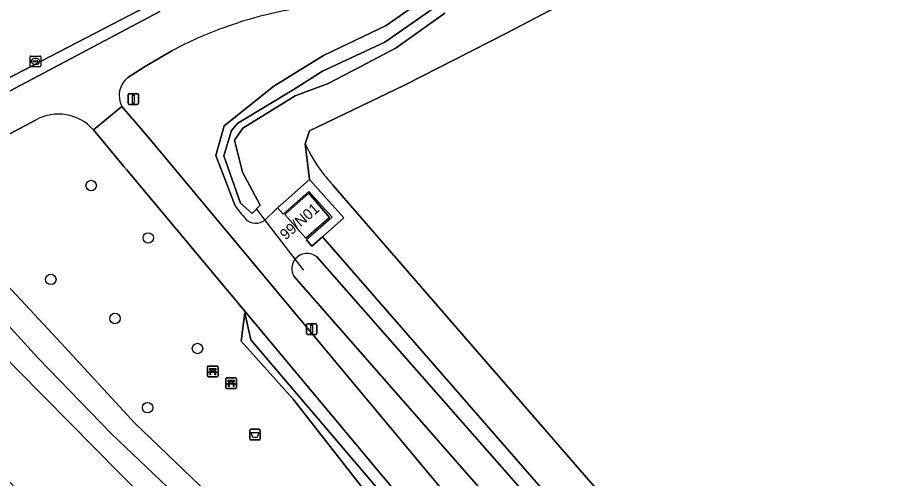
# Model space of a CAD drawing. Extents: x 156061 to 157804, y 383437 to 385640.
# Drawn here: x 156111.7 to 156194.1, y 385328.5 to 385371.7 of the extents above; entities that cross this region are included whole.
import ezdxf

# ---------------------------------------------------------------- set-up
doc = ezdxf.new("R2010")
doc.units = 0
for name, color, linetype in [('IMGEO_Afvalbak', 7, 'Continuous'), ('IMGEO_Bank', 7, 'Continuous'), ('IMGEO_Berm_groen', 7, 'Continuous'), ('IMGEO_Boom', 7, 'Continuous'), ('IMGEO_Duiker', 7, 'Continuous'), ('IMGEO_Fietspad_gesloten', 7, 'Continuous'), ('IMGEO_Groenvoorziening', 7, 'Continuous'), ('IMGEO_Kolk', 7, 'Continuous'), ('IMGEO_Lichtmast', 7, 'Continuous'), ('IMGEO_Loofbos', 7, 'Continuous'), ('IMGEO_Muur', 7, 'Continuous'), ('IMGEO_Oever', 7, 'Continuous'), ('IMGEO_Pand', 7, 'Continuous'), ('IMGEO_Pand_nummerreeks', 7, 'Continuous'), ('IMGEO_Rijbaan_lokaal_gesloten', 7, 'Continuous'), ('IMGEO_Rijbaan_lokaal_open', 7, 'Continuous'), ('IMGEO_Rijbaan_regionaal_gesloten', 7, 'Continuous'), ('IMGEO_Waterloop', 7, 'Continuous')]:
    doc.layers.add(name, color=color, linetype=linetype)

msp = doc.modelspace()

# ---------------------------------------------------------------- linework, layer by layer
at = {"layer": 'IMGEO_Afvalbak'}
for p, q in [((156133.502, 385332.24), (156133.502, 385333.04)), ((156133.502, 385333.04), (156133.502, 385332.24)), ((156133.602, 385333.14), (156134.392, 385333.14)), ((156134.392, 385333.14), (156133.602, 385333.14)), ((156134.492, 385333.04), (156134.492, 385332.24)), ((156134.492, 385332.24), (156134.492, 385333.04)), ((156134.392, 385332.14), (156133.602, 385332.14)), ((156133.602, 385332.14), (156134.392, 385332.14))]:
    msp.add_line(p, q, dxfattribs=at)
msp.add_lwpolyline([(156133.645, 385332.854), (156134.349, 385332.854), (156134.2, 385332.384), (156133.794, 385332.384), (156133.645, 385332.854)], dxfattribs=at)
for centre, start, end in [((156133.602, 385333.04), 90, 180), ((156133.602, 385333.04), 90, 180), ((156134.392, 385333.04), 0, 90), ((156134.392, 385333.04), 360, 90), ((156133.602, 385332.24), 180, 270), ((156133.602, 385332.24), 180, 270), ((156134.392, 385332.24), 270, 0), ((156134.392, 385332.24), 270, 0)]:
    msp.add_arc(centre, 0.1, start, end, dxfattribs=at)
at = {"layer": 'IMGEO_Bank'}
for p, q in [((156129.534, 385338.142), (156129.534, 385338.983)), ((156129.534, 385338.983), (156129.534, 385338.142)), ((156129.609, 385339.067), (156130.45, 385339.067)), ((156130.45, 385339.067), (156129.609, 385339.067)), ((156130.231, 385338.465), (156129.838, 385338.465)), ((156129.843, 385338.573), (156129.843, 385338.679)), ((156129.887, 385338.679), (156129.887, 385338.573)), ((156130.175, 385338.685), (156129.893, 385338.685)), ((156129.893, 385338.567), (156130.175, 385338.567)), ((156130.181, 385338.573), (156130.181, 385338.679)), ((156130.225, 385338.679), (156130.225, 385338.573)), ((156130.534, 385338.992), (156130.534, 385338.151)), ((156130.534, 385338.151), (156130.534, 385338.992)), ((156130.459, 385338.067), (156129.618, 385338.067)), ((156129.618, 385338.067), (156130.459, 385338.067)), ((156131.264, 385337.033), (156131.264, 385337.874)), ((156131.264, 385337.874), (156131.264, 385337.033)), ((156131.339, 385337.958), (156132.18, 385337.958)), ((156132.18, 385337.958), (156131.339, 385337.958)), ((156132.264, 385337.883), (156132.264, 385337.042)), ((156132.264, 385337.042), (156132.264, 385337.883)), ((156132.189, 385336.958), (156131.348, 385336.958)), ((156131.348, 385336.958), (156132.189, 385336.958)), ((156131.961, 385337.356), (156131.568, 385337.356)), ((156131.573, 385337.464), (156131.573, 385337.57)), ((156131.617, 385337.57), (156131.617, 385337.464)), ((156131.905, 385337.576), (156131.623, 385337.576)), ((156131.623, 385337.458), (156131.905, 385337.458)), ((156131.911, 385337.464), (156131.911, 385337.57)), ((156131.955, 385337.57), (156131.955, 385337.464))]:
    msp.add_line(p, q, dxfattribs=at)
for points in [[(156129.781, 385338.465), (156129.639, 385338.465), (156129.751, 385338.567), (156129.837, 385338.567)], [(156129.837, 385338.685), (156129.751, 385338.685), (156129.751, 385338.846), (156130.314, 385338.846), (156130.314, 385338.685), (156130.231, 385338.685)], [(156129.831, 385338.458), (156129.831, 385338.251), (156129.788, 385338.251), (156129.788, 385338.458)], [(156130.231, 385338.567), (156130.314, 385338.567), (156130.426, 385338.465), (156130.287, 385338.465)], [(156130.281, 385338.458), (156130.281, 385338.251), (156130.237, 385338.251), (156130.237, 385338.458)], [(156131.567, 385337.576), (156131.481, 385337.576), (156131.481, 385337.737), (156132.044, 385337.737), (156132.044, 385337.576), (156131.961, 385337.576)], [(156131.511, 385337.356), (156131.369, 385337.356), (156131.481, 385337.458), (156131.567, 385337.458)], [(156131.561, 385337.349), (156131.561, 385337.142), (156131.518, 385337.142), (156131.518, 385337.349)], [(156131.961, 385337.458), (156132.044, 385337.458), (156132.156, 385337.356), (156132.017, 385337.356)], [(156132.011, 385337.349), (156132.011, 385337.142), (156131.967, 385337.142), (156131.967, 385337.349)]]:
    msp.add_lwpolyline(points, dxfattribs=at)
for centre, radius, start, end in [((156129.612, 385338.989), 0.0779, 92.4484, 184.28452), ((156129.612, 385338.989), 0.0779, 92.4484, 184.28452), ((156129.781, 385338.458), 0.00671, 2.89567, 87.10433), ((156129.838, 385338.458), 0.00671, 92.89567, 177.10433), ((156129.836, 385338.678), 0.00671, 2.89567, 87.10433), ((156129.836, 385338.574), 0.00671, 272.89567, 357.10433), ((156129.893, 385338.678), 0.00671, 92.89567, 177.10433), ((156129.893, 385338.574), 0.00671, 182.89567, 267.10433), ((156130.175, 385338.678), 0.00671, 2.89567, 87.10433), ((156130.175, 385338.574), 0.00671, 272.89567, 357.10433), ((156130.232, 385338.678), 0.00671, 92.89567, 177.10433), ((156130.232, 385338.574), 0.00671, 182.89567, 267.10433), ((156130.23, 385338.458), 0.00671, 2.89567, 87.10433), ((156130.287, 385338.458), 0.00671, 92.89567, 177.10433), ((156130.456, 385338.989), 0.0779, 2.4484, 94.28452), ((156130.456, 385338.989), 0.0779, 2.4484, 94.28452), ((156129.612, 385338.145), 0.0779, 182.4484, 274.28452), ((156129.612, 385338.145), 0.0779, 182.4484, 274.28452), ((156130.456, 385338.145), 0.0779, 272.4484, 4.28452), ((156130.456, 385338.145), 0.0779, 272.4484, 4.28452), ((156131.342, 385337.88), 0.0779, 92.4484, 184.28452), ((156131.342, 385337.88), 0.0779, 92.4484, 184.28452), ((156132.186, 385337.88), 0.0779, 2.4484, 94.28452), ((156132.186, 385337.88), 0.0779, 2.4484, 94.28452), ((156131.342, 385337.036), 0.0779, 182.4484, 274.28452), ((156131.342, 385337.036), 0.0779, 182.4484, 274.28452), ((156131.511, 385337.349), 0.00671, 2.89567, 87.10433), ((156131.568, 385337.349), 0.00671, 92.89567, 177.10433), ((156131.566, 385337.569), 0.00671, 2.89567, 87.10433), ((156131.566, 385337.465), 0.00671, 272.89567, 357.10433), ((156131.623, 385337.569), 0.00671, 92.89567, 177.10433), ((156131.623, 385337.465), 0.00671, 182.89567, 267.10433), ((156131.905, 385337.569), 0.00671, 2.89567, 87.10433), ((156131.905, 385337.465), 0.00671, 272.89567, 357.10433), ((156131.962, 385337.569), 0.00671, 92.89567, 177.10433), ((156131.962, 385337.465), 0.00671, 182.89567, 267.10433), ((156131.96, 385337.349), 0.00671, 2.89567, 87.10433), ((156132.017, 385337.349), 0.00671, 92.89567, 177.10433), ((156132.186, 385337.036), 0.0779, 272.4484, 4.28452), ((156132.186, 385337.036), 0.0779, 272.4484, 4.28452)]:
    msp.add_arc(centre, radius, start, end, dxfattribs=at)
at = {"layer": 'IMGEO_Berm_groen'}
msp.add_lwpolyline([(156362.884, 385518.973), (156357.592, 385515.726), (156355.546, 385514.471), (156333.022, 385500.076), (156304.543, 385485.405), (156304.354, 385485.797), (156253.2, 385452.656), (156166.982, 385396.482), (156160.762, 385392.485), (156159.544, 385391.815), (156159.731, 385391.428), (156152.382, 385387.554), (156100.569, 385360.692), (156097.06, 385358.974), (156097.829, 385357.837), (156097.994, 385357.927), (156125.069, 385372.264)], dxfattribs=at)
at = {"layer": 'IMGEO_Boom'}
for centre in [(156118.643, 385355.969), (156123.994, 385351.065), (156114.858, 385347.18), (156120.874, 385343.522), (156128.607, 385340.709), (156123.933, 385335.169)]:
    msp.add_circle(centre, 0.489, dxfattribs=at)
at = {"layer": 'IMGEO_Duiker'}
msp.add_lwpolyline([(156134.122, 385353.757), (156134.914, 385352.731), (156137.743, 385349.064), (156138.528, 385348.047)], dxfattribs=at)
at = {"layer": 'IMGEO_Fietspad_gesloten'}
for points in [[(156125.069, 385372.264), (156097.994, 385357.927), (156097.829, 385357.837), (156095.409, 385356.512), (156096.045, 385355.752), (156098.015, 385353.552), (156101.468, 385355.413), (156101.871, 385355.645), (156108.986, 385359.742), (156113.433, 385362.1)], [(156122.086, 385366.08), (156123.812, 385367.192), (156126.209, 385368.594)], [(156124.171, 385360.272), (156123.473, 385361.108), (156121.522, 385363.38), (156118.856, 385361.174), (156121.706, 385357.754), (156121.942, 385357.471), (156177.328, 385291.209)], [(156118.856, 385361.174), (156121.522, 385363.38)], [(156180.981, 385292.496), (156180.803, 385292.737), (156151.782, 385327.202), (156124.171, 385360.272)]]:
    msp.add_lwpolyline(points, dxfattribs=at)
for centre, radius, start, end in [((156144.397, 385334.134), 38.966, 100.19662, 109.99344), ((156144.386, 385334.178), 38.921, 110.00054, 117.84136), ((156123.412, 385364.394), 2.145, 128.18771, 208.2147), ((156115.576, 385358.305), 4.358, 41.16871, 119.45122)]:
    msp.add_arc(centre, radius, start, end, dxfattribs=at)
at = {"layer": 'IMGEO_Groenvoorziening'}
for points in [[(156132.124, 385354.072), (156130.332, 385358.77), (156131.122, 385361.565), (156135.769, 385365.262), (156140.41, 385368.141), (156146.274, 385370.967), (156151.561, 385374.676)], [(156126.209, 385368.594), (156123.812, 385367.192), (156122.086, 385366.08)], [(156121.522, 385363.38), (156123.473, 385361.108), (156124.171, 385360.272), (156151.782, 385327.202)], [(156113.433, 385362.1), (156108.986, 385359.742)], [(156177.328, 385291.209), (156121.942, 385357.471), (156121.706, 385357.754), (156118.856, 385361.174)], [(156138.687, 385359.878), (156139.112, 385356.54), (156142.328, 385352.959), (156140.316, 385351.172), (156228.502, 385250), (156247.683, 385227.995), (156253.968, 385221.655), (156275.143, 385200.293), (156292.679, 385186.81), (156309.519, 385180.688), (156293.366, 385188.187), (156275.563, 385201.731)], [(156275.563, 385201.731), (156250.074, 385230.682), (156233.307, 385250), (156141.333, 385355.967)], [(156308.967, 385179.207), (156309.519, 385180.688), (156292.679, 385186.81), (156275.143, 385200.293), (156253.968, 385221.655), (156247.683, 385227.995), (156228.502, 385250), (156140.316, 385351.172), (156139.329, 385350.295), (156138.808, 385350.896), (156141.213, 385353.008), (156139.055, 385355.418), (156136.634, 385353.281), (156136.104, 385353.881), (156134.914, 385352.731)], [(156132.278, 385307.447), (156166.281, 385278.086), (156168.774, 385281.118), (156168.451, 385282.676), (156168.153, 385284.113), (156128.476, 385321.756), (156111.805, 385338.65), (156108.949, 385341.526), (156101.165, 385350.479), (156102.695, 385354.328), (156092.828, 385348.213)], [(156106.557, 385351.121), (156115.827, 385341.223), (156122.749, 385333.724), (156145.451, 385311.967), (156161.597, 385296.852), (156167.136, 385291.02), (156170.907, 385294.205), (156167.577, 385298.602), (156152.558, 385316.809)], [(156108.949, 385341.526), (156111.805, 385338.65), (156128.476, 385321.756), (156168.153, 385284.113), (156168.051, 385284.608), (156168.579, 385286.057), (156165.732, 385289.28), (156159.247, 385295.892), (156120.561, 385332.702), (156113.657, 385339.835), (156104.831, 385349.468)], [(156139.813, 385349.261), (156227.178, 385250)], [(156244.566, 385225.657), (156223.173, 385250), (156160.289, 385321.652), (156137.62, 385347.482)], [(156152.558, 385316.809), (156137.58, 385335.954), (156132.713, 385341.392), (156133.03, 385344.043), (156133.592, 385341.527), (156173.944, 385294.235), (156176.282, 385291.491)]]:
    msp.add_lwpolyline(points, dxfattribs=at)
msp.add_lwpolyline([(156140.985, 385352.992), (156138.774, 385351.041), (156136.784, 385353.269), (156139.027, 385355.243)], close=True, dxfattribs=at)
for centre, radius, start, end in [((156144.397, 385334.134), 38.966, 100.19662, 109.99344), ((156144.386, 385334.178), 38.921, 110.00054, 117.84136), ((156123.412, 385364.394), 2.145, 128.18771, 208.2147), ((156115.576, 385358.305), 4.358, 41.16871, 119.45122), ((156153.941, 385367.252), 16.943, 205.79963, 217.02343), ((156153.76, 385367.443), 16.915, 217.91063, 222.72317), ((156145.275, 385363.705), 16.302, 216.22196, 221.88639), ((156134.079, 385353.813), 1.366, 226.53175, 307.66295), ((156138.871, 385348.189), 1.427, 48.66865, 142.20418), ((156138.862, 385348.181), 1.425, 141.72781, 209.38062), ((156444.762, 385648.913), 462.867, 222.80362, 227.53759)]:
    msp.add_arc(centre, radius, start, end, dxfattribs=at)
at = {"layer": 'IMGEO_Kolk'}
for p, q in [((156112.991, 385368.095), (156113.843, 385368.095)), ((156112.916, 385367.169), (156112.916, 385368.021)), ((156113.175, 385367.589), (156113.175, 385367.601)), ((156113.613, 385367.552), (156113.215, 385367.552)), ((156113.218, 385367.638), (156113.616, 385367.638)), ((156113.427, 385367.315), (156113.402, 385367.315)), ((156113.404, 385367.875), (156113.429, 385367.875)), ((156113.659, 385367.601), (156113.659, 385367.589)), ((156113.917, 385368.021), (156113.917, 385367.169)), ((156113.843, 385367.095), (156112.991, 385367.095))]:
    msp.add_line(p, q, dxfattribs=at)
for points in [[(156112.991, 385368.095), (156113.843, 385368.095)], [(156112.916, 385367.169), (156112.916, 385368.021)], [(156113.917, 385368.021), (156113.917, 385367.169)], [(156113.843, 385367.095), (156112.991, 385367.095)]]:
    msp.add_lwpolyline(points, dxfattribs=at)
for centre, radius, start, end in [((156112.993, 385368.019), 0.0765, 91.55205, 178.44795), ((156112.993, 385368.019), 0.0765, 91.55205, 178.44795), ((156113.841, 385368.019), 0.0765, 1.55205, 88.44795), ((156113.841, 385368.019), 0.0765, 1.55205, 88.44795), ((156113.215, 385367.598), 0.0403, 85.87752, 175.75265), ((156113.212, 385367.588), 0.0366, 178.93798, 274.71019), ((156113.616, 385367.595), 0.043, 264.86636, 352.45326), ((156113.62, 385367.6), 0.0386, 1.73085, 96.63898), ((156112.993, 385367.171), 0.0765, 181.55205, 268.44795), ((156112.993, 385367.171), 0.0765, 181.55205, 268.44795), ((156113.841, 385367.171), 0.0765, 271.55205, 358.44795), ((156113.841, 385367.171), 0.0765, 271.55205, 358.44795)]:
    msp.add_arc(centre, radius, start, end, dxfattribs=at)
for centre, major_axis, ratio, start_param, end_param in [((156113.403, 385367.595), (-0.387, 0.002), 0.722429, 4.712389, 7.853982), ((156113.428, 385367.595), (-0.39, 0.002), 0.717154, 1.570796, 4.712389)]:
    msp.add_ellipse(centre, major_axis=major_axis, ratio=ratio, start_param=start_param, end_param=end_param, dxfattribs=at)
at = {"layer": 'IMGEO_Lichtmast'}
for p, q in [((156122.098, 385363.672), (156122.098, 385364.472)), ((156122.098, 385364.472), (156122.098, 385363.672)), ((156122.198, 385364.572), (156122.988, 385364.572)), ((156122.988, 385364.572), (156122.198, 385364.572)), ((156123.088, 385364.472), (156123.088, 385363.672)), ((156123.088, 385363.672), (156123.088, 385364.472)), ((156122.988, 385363.572), (156122.198, 385363.572)), ((156122.198, 385363.572), (156122.988, 385363.572)), ((156138.814, 385342.126), (156138.814, 385342.926)), ((156138.814, 385342.926), (156138.814, 385342.126)), ((156138.914, 385343.026), (156139.704, 385343.026)), ((156139.704, 385343.026), (156138.914, 385343.026)), ((156139.804, 385342.926), (156139.804, 385342.126)), ((156139.804, 385342.126), (156139.804, 385342.926)), ((156139.704, 385342.026), (156138.914, 385342.026)), ((156138.914, 385342.026), (156139.704, 385342.026))]:
    msp.add_line(p, q, dxfattribs=at)
for points in [[(156122.518, 385364.447), (156122.668, 385364.447), (156122.668, 385363.697), (156122.518, 385363.697), (156122.518, 385364.447)], [(156139.234, 385342.901), (156139.384, 385342.901), (156139.384, 385342.151), (156139.234, 385342.151), (156139.234, 385342.901)]]:
    msp.add_lwpolyline(points, dxfattribs=at)
for centre, start, end in [((156122.198, 385364.472), 90, 180), ((156122.198, 385364.472), 90, 180), ((156122.988, 385364.472), 0, 90), ((156122.988, 385364.472), 360, 90), ((156122.198, 385363.672), 180, 270), ((156122.198, 385363.672), 180, 270), ((156122.988, 385363.672), 270, 0), ((156122.988, 385363.672), 270, 0), ((156138.914, 385342.926), 90, 180), ((156138.914, 385342.926), 90, 180), ((156139.704, 385342.926), 0, 90), ((156139.704, 385342.926), 360, 90), ((156138.914, 385342.126), 180, 270), ((156138.914, 385342.126), 180, 270), ((156139.704, 385342.126), 270, 0), ((156139.704, 385342.126), 270, 0)]:
    msp.add_arc(centre, 0.1, start, end, dxfattribs=at)
at = {"layer": 'IMGEO_Loofbos'}
for points in [[(156209.431, 385312.369), (156207.265, 385318.028), (156200.466, 385373.294), (156194.259, 385390.622), (156192.986, 385389.689), (156188.262, 385386.889), (156182.837, 385384.089), (156174.438, 385379.365), (156166.739, 385375.078), (156157.64, 385370.266), (156148.016, 385365.366), (156139.092, 385361.079), (156138.687, 385359.878)], [(156141.333, 385355.967), (156233.307, 385250), (156250.074, 385230.682), (156275.563, 385201.731), (156293.366, 385188.187), (156309.519, 385180.688), (156322.018, 385207.14), (156273.471, 385237.156), (156244.765, 385266.89), (156209.431, 385312.369)], [(156169.099, 385287.885), (156166.982, 385289.627), (156169.116, 385291.28), (156173.944, 385294.235), (156133.592, 385341.527), (156133.03, 385344.043), (156132.713, 385341.392), (156137.58, 385335.954), (156152.558, 385316.809), (156167.577, 385298.602), (156170.907, 385294.205), (156167.136, 385291.02), (156161.597, 385296.852), (156145.451, 385311.967), (156122.749, 385333.724), (156115.827, 385341.223), (156106.557, 385351.121)], [(156104.831, 385349.468), (156113.657, 385339.835), (156120.561, 385332.702), (156159.247, 385295.892), (156165.732, 385289.28), (156168.579, 385286.057), (156168.051, 385284.608), (156168.153, 385284.113), (156168.451, 385282.676), (156169.004, 385283.259), (156169.907, 385285.17)]]:
    msp.add_lwpolyline(points, dxfattribs=at)
for centre, radius, start, end in [((156153.941, 385367.252), 16.943, 205.79963, 217.02343), ((156153.76, 385367.443), 16.915, 217.91063, 222.72317)]:
    msp.add_arc(centre, radius, start, end, dxfattribs=at)
at = {"layer": 'IMGEO_Muur'}
msp.add_lwpolyline([(156142.328, 385352.959), (156139.112, 385356.54), (156137.153, 385354.808), (156136.104, 385353.881), (156136.634, 385353.281), (156139.055, 385355.418), (156141.213, 385353.008), (156138.808, 385350.896), (156139.329, 385350.295), (156140.316, 385351.172)], close=True, dxfattribs=at)
at = {"layer": 'IMGEO_Oever'}
for points in [[(156134.914, 385352.731), (156136.104, 385353.881), (156137.153, 385354.808), (156139.112, 385356.54), (156138.687, 385359.878), (156139.092, 385361.079), (156148.016, 385365.366), (156157.64, 385370.266), (156166.739, 385375.078), (156174.438, 385379.365), (156182.837, 385384.089), (156188.262, 385386.889), (156192.986, 385389.689)], [(156151.561, 385374.676), (156146.274, 385370.967), (156140.41, 385368.141), (156135.769, 385365.262), (156131.122, 385361.565), (156130.332, 385358.77), (156132.124, 385354.072)], [(156151.778, 385372.103), (156147.229, 385368.866), (156143.904, 385367.116), (156140.842, 385365.541), (156137.763, 385364.363), (156132.846, 385361.334), (156132.071, 385360.226), (156132.837, 385357.208), (156134.477, 385354.146), (156133.734, 385353.336), (156132.64, 385354.321), (156131.065, 385358.761), (156131.809, 385361.123), (156132.395, 385361.805), (156137.577, 385364.943), (156140.317, 385366.679), (156146.179, 385369.391), (156152.128, 385373.59)]]:
    msp.add_lwpolyline(points, dxfattribs=at)
for centre, radius, start, end in [((156145.275, 385363.705), 16.302, 216.22196, 221.88639), ((156134.079, 385353.813), 1.366, 226.53175, 307.66295)]:
    msp.add_arc(centre, radius, start, end, dxfattribs=at)
at = {"layer": 'IMGEO_Pand'}
msp.add_lwpolyline([(156138.774, 385351.041), (156140.985, 385352.992), (156139.027, 385355.243), (156136.784, 385353.269)], close=True, dxfattribs=at)
at = {"layer": 'IMGEO_Rijbaan_lokaal_gesloten'}
msp.add_arc((156441.097, 385645.969), 458.462, 222.83854, 227.62493, dxfattribs=at)
at = {"layer": 'IMGEO_Rijbaan_lokaal_open'}
for centre, radius, start, end in [((156444.762, 385648.913), 462.867, 222.80362, 227.53759), ((156441.097, 385645.969), 458.462, 222.83854, 227.62493)]:
    msp.add_arc(centre, radius, start, end, dxfattribs=at)
at = {"layer": 'IMGEO_Rijbaan_regionaal_gesloten'}
msp.add_lwpolyline([(156355.546, 385514.471), (156357.592, 385515.726), (156347.87, 385530.832), (156281.687, 385487.986), (156224.676, 385450.976), (156145.76, 385399.909), (156093.268, 385365.389), (156089.856, 385363.151), (156095.262, 385356.688), (156095.409, 385356.512), (156097.829, 385357.837), (156097.06, 385358.974), (156100.569, 385360.692), (156152.382, 385387.554), (156159.731, 385391.428), (156159.544, 385391.815), (156160.762, 385392.485), (156166.982, 385396.482), (156253.2, 385452.656), (156304.354, 385485.797), (156304.543, 385485.405), (156333.022, 385500.076)], close=True, dxfattribs=at)
at = {"layer": 'IMGEO_Waterloop'}
for points in [[(156152.128, 385373.59), (156146.179, 385369.391), (156140.317, 385366.679), (156137.577, 385364.943), (156132.395, 385361.805), (156131.809, 385361.123), (156131.065, 385358.761), (156132.64, 385354.321), (156133.734, 385353.336), (156134.477, 385354.146), (156132.837, 385357.208), (156132.071, 385360.226), (156132.846, 385361.334), (156137.763, 385364.363), (156140.842, 385365.541), (156143.904, 385367.116), (156147.229, 385368.866), (156151.778, 385372.103)], [(156246.807, 385227.708), (156227.178, 385250), (156139.813, 385349.261)], [(156137.62, 385347.482), (156160.289, 385321.652), (156223.173, 385250), (156244.566, 385225.657)]]:
    msp.add_lwpolyline(points, dxfattribs=at)
for centre, radius, start, end in [((156138.871, 385348.189), 1.427, 48.66865, 142.20418), ((156138.862, 385348.181), 1.425, 141.72781, 209.38062)]:
    msp.add_arc(centre, radius, start, end, dxfattribs=at)

# ---------------------------------------------------------------- texts
at = {"layer": 'IMGEO_Pand_nummerreeks'}
msp.add_text('99/N01', height=1, rotation=40.99178, dxfattribs=at).set_placement((156136.864, 385350.819))

doc.saveas('drawing.dxf')
